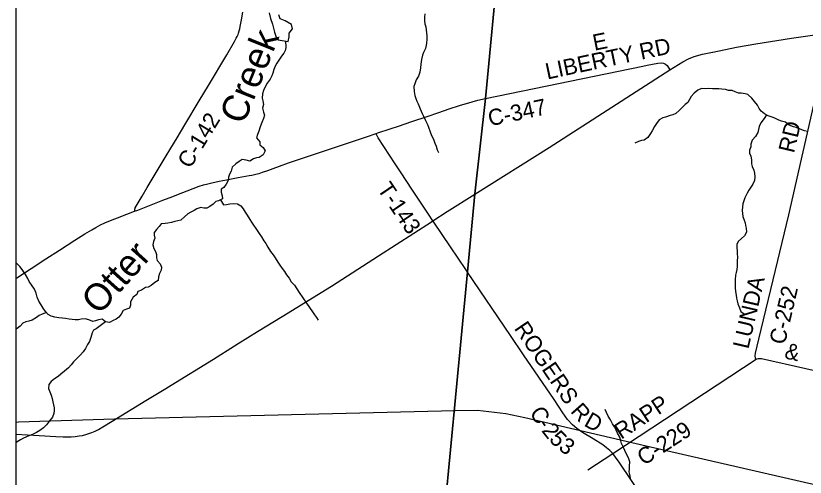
# Model space of a CAD drawing. Extents: x 0 to 34, y 0 to 22.
# Drawn here: x 2.1 to 3.488, y 15.74 to 16.551 of the extents above; entities that cross this region are included whole.
import ezdxf

# ---------------------------------------------------------------- set-up
doc = ezdxf.new("R2010")
doc.units = 0
for name, color, linetype in [('GM_X_Corporation', 7, 'Continuous'), ('GM_X_County_Road', 7, 'Continuous'), ('GM_X_County_Road_Text', 7, 'Continuous'), ('GM_X_Minor_Lake', 7, 'Continuous'), ('GM_X_Minor_River', 7, 'Continuous'), ('GM_X_Minor_River_Text', 7, 'Continuous'), ('GM_X_Rail_Line', 7, 'Continuous'), ('GM_X_State_Location', 7, 'Continuous'), ('GM_X_State_Route', 7, 'Continuous'), ('GM_X_Township_Road', 7, 'Continuous'), ('GM_X_Township_Road_Text', 7, 'Continuous'), ('SH_Data', 7, 'Continuous')]:
    doc.layers.add(name, color=color, linetype=linetype)

msp = doc.modelspace()

# ---------------------------------------------------------------- linework, layer by layer
at = {"layer": 'GM_X_Corporation'}
for points in [[(2.8444, 15.5792), (2.8939, 16.1007), (2.9069, 16.2381), (2.9254, 16.4061), (2.988, 17.0603), (3.0331, 17.5172), (3.0637, 17.8164), (3.0931, 18.1263), (3.1112, 18.3014), (3.1559, 18.7686), (3.1859, 19.0395), (3.2287, 19.5029), (3.2417, 19.6403), (3.2592, 19.8236), (3.2953, 20.1573), (3.3575, 20.7908), (3.3687, 20.9), (2.1, 20.9), (2.1, 14.1)], [(8.9, 20.9), (3.3687, 20.9), (3.3575, 20.7908), (3.2953, 20.1573), (3.2592, 19.8236), (3.2417, 19.6403), (3.2287, 19.5029), (3.1859, 19.0395), (3.1559, 18.7686), (3.1112, 18.3014), (3.0931, 18.1263), (3.0637, 17.8164), (3.0331, 17.5172), (2.988, 17.0603), (2.9254, 16.4061), (2.9069, 16.2381), (2.8939, 16.1007), (2.8444, 15.5792)]]:
    msp.add_lwpolyline(points, dxfattribs=at)
msp.add_lwpolyline([(2.1, 18.2085), (2.1, 15.0365), (2.12, 15.0353), (2.1206, 15.0353), (2.1394, 15.0344), (2.1436, 15.0342), (2.148, 15.0339), (2.791, 14.9974), (2.8444, 15.5792), (2.8939, 16.1007), (2.9069, 16.2381), (2.9254, 16.4061), (2.988, 17.0603), (3.0331, 17.5172), (3.0637, 17.8164), (3.0931, 18.1263), (3.0252, 18.1335), (2.8083, 18.1509), (2.4093, 18.1831), (2.1311, 18.2055)], close=True, dxfattribs=at)
at = {"layer": 'GM_X_County_Road'}
msp.add_line((3.1053, 15.7527), (3.1492, 15.7812), dxfattribs=at)
for points in [[(2.3089, 16.2074), (2.309, 16.2091), (2.3091, 16.2106), (2.3093, 16.2116), (2.3096, 16.2126), (2.31, 16.2138), (2.3131, 16.2193), (2.3221, 16.2342), (2.3312, 16.2495), (2.3468, 16.2756), (2.3628, 16.3022), (2.3725, 16.3185), (2.3835, 16.3369), (2.3969, 16.3593), (2.4224, 16.402), (2.4385, 16.4289), (2.4707, 16.4828), (2.4844, 16.5061), (2.4876, 16.5118), (2.4893, 16.5151), (2.4906, 16.5182), (2.4915, 16.5206), (2.4928, 16.5251), (2.4938, 16.5285), (2.4946, 16.5325), (2.4968, 16.5441), (2.4993, 16.5579)], [(3.4013, 15.9472), (3.4005, 15.9491), (3.3995, 15.953), (3.4, 15.9576), (3.4061, 15.9827), (3.4354, 16.1039), (3.4589, 16.2013), (3.5314, 16.5205)], [(2.9255, 16.4059), (3.2023, 16.4627), (3.2098, 16.4642)], [(3.2098, 16.4642), (3.2285, 16.4679), (3.2351, 16.4686), (3.2388, 16.4679), (3.2419, 16.4664), (3.2449, 16.4638), (3.2499, 16.4562)], [(2.1, 16.0891), (2.102, 16.0904), (2.1271, 16.1066), (2.1531, 16.1236), (2.1768, 16.139), (2.2039, 16.1567), (2.2212, 16.1676), (2.2334, 16.175), (2.2407, 16.1791), (2.249, 16.1834), (2.2568, 16.187), (2.2695, 16.1923), (2.2787, 16.196), (2.2952, 16.2022), (2.3089, 16.2074), (2.3144, 16.2095), (2.341, 16.22), (2.3587, 16.2268), (2.3758, 16.2334), (2.383, 16.2363), (2.412, 16.2476), (2.4221, 16.2514), (2.4301, 16.254), (2.4375, 16.256), (2.4445, 16.2577), (2.4576, 16.2603), (2.4701, 16.2626), (2.4911, 16.2667), (2.5103, 16.2702), (2.5151, 16.2712), (2.5197, 16.2722), (2.5241, 16.2732), (2.5277, 16.2742), (2.5339, 16.2761), (2.5428, 16.2792), (2.5525, 16.2829), (2.5637, 16.2871), (2.5792, 16.2925), (2.6148, 16.3047), (2.6481, 16.3158), (2.6709, 16.3233), (2.7163, 16.3386), (2.7335, 16.3444), (2.7365, 16.3454), (2.758, 16.3527), (2.7725, 16.3574), (2.796, 16.3652), (2.8233, 16.3744), (2.8435, 16.3812), (2.8619, 16.3874), (2.88, 16.3935), (2.9022, 16.3999), (2.9124, 16.4027), (2.9255, 16.4059)], [(3.1492, 15.7812), (3.1442, 15.7865), (3.1383, 15.7916), (3.1316, 15.7966), (3.1148, 15.8072), (3.0961, 15.8185), (3.0864, 15.8252), (3.0788, 15.8318), (3.0698, 15.8415), (3.0618, 15.8528), (3.0461, 15.8761), (2.9926, 15.9551), (2.9695, 15.9892), (2.894, 16.1004)], [(3.1492, 15.7812), (3.4013, 15.9472), (3.4056, 15.9484), (3.4107, 15.9484), (3.4889, 15.9308), (3.6071, 15.9041), (3.932, 15.83), (4.1105, 15.7887), (4.468, 15.7031), (4.4755, 15.701), (4.4802, 15.6984), (4.484, 15.6949)], [(3.2487, 15.6355), (3.1608, 15.7663), (3.1543, 15.7752), (3.1492, 15.7812)]]:
    msp.add_lwpolyline(points, dxfattribs=at)
at = {"layer": 'GM_X_Minor_Lake'}
msp.add_lwpolyline([(2.5454, 16.5563), (2.5476, 16.5466), (2.551, 16.5368), (2.5547, 16.5223), (2.5578, 16.5135), (2.5612, 16.5093), (2.5786, 16.506), (2.5808, 16.5143), (2.5806, 16.5206), (2.5866, 16.5282), (2.5846, 16.5362), (2.5737, 16.5423), (2.565, 16.5461), (2.5621, 16.5533)], dxfattribs=at)
at = {"layer": 'GM_X_Minor_River'}
for points in [[(2.8189, 16.5548), (2.8184, 16.5489), (2.8183, 16.5426), (2.8193, 16.5371), (2.8208, 16.5321), (2.8216, 16.5264), (2.8221, 16.5213), (2.8226, 16.5158), (2.8225, 16.5109), (2.8219, 16.5027), (2.8203, 16.4936), (2.8167, 16.4868), (2.8151, 16.4819), (2.8133, 16.4746), (2.812, 16.4662), (2.8111, 16.46), (2.8102, 16.4524), (2.8076, 16.4454), (2.8039, 16.4387), (2.8013, 16.4319), (2.7999, 16.4268), (2.8003, 16.4184), (2.8017, 16.411), (2.8029, 16.406), (2.8051, 16.4011), (2.8071, 16.3963), (2.8108, 16.3879), (2.8146, 16.3794), (2.8165, 16.3747), (2.8199, 16.3674), (2.8236, 16.3603), (2.8254, 16.3555), (2.8283, 16.3473), (2.8309, 16.3406), (2.834, 16.3341), (2.8364, 16.3274), (2.8389, 16.3221), (2.8409, 16.3158), (2.8433, 16.311)], [(2.5741, 16.5068), (2.5746, 16.4965), (2.574, 16.4916), (2.5712, 16.4854), (2.5669, 16.4805), (2.5634, 16.4749), (2.5591, 16.4682), (2.556, 16.4629), (2.5536, 16.4567), (2.5516, 16.4506), (2.5502, 16.4457), (2.5472, 16.4399), (2.5421, 16.4329), (2.5378, 16.425), (2.5353, 16.42), (2.5334, 16.4139), (2.5331, 16.4063), (2.5345, 16.4016), (2.5352, 16.3953), (2.5339, 16.3889), (2.5357, 16.382), (2.5373, 16.3766), (2.5353, 16.3704), (2.5325, 16.3634), (2.5297, 16.3559), (2.5271, 16.3483), (2.525, 16.3425), (2.5231, 16.3366), (2.5287, 16.3295), (2.5292, 16.3242), (2.5346, 16.3197), (2.5383, 16.3136), (2.5346, 16.3068), (2.5277, 16.3018), (2.5229, 16.3015), (2.5177, 16.2999), (2.5116, 16.2958), (2.5051, 16.2975), (2.4981, 16.2985), (2.4929, 16.2952), (2.487, 16.2909), (2.4802, 16.2848), (2.4788, 16.2782), (2.4758, 16.2725), (2.474, 16.2673), (2.4733, 16.2619), (2.4696, 16.2554), (2.4659, 16.2495), (2.4611, 16.2466), (2.4612, 16.2413), (2.463, 16.2344), (2.4633, 16.2295), (2.4563, 16.2258), (2.4516, 16.2245), (2.4467, 16.2199), (2.4413, 16.216), (2.4358, 16.2132), (2.4303, 16.2131), (2.425, 16.2144), (2.4184, 16.2118), (2.4133, 16.2089), (2.4077, 16.2059), (2.4027, 16.2032), (2.3963, 16.1978), (2.3901, 16.192), (2.3848, 16.1904), (2.3796, 16.1893), (2.3737, 16.1875), (2.3674, 16.1863), (2.3627, 16.186), (2.3554, 16.1856), (2.3519, 16.1807), (2.3476, 16.1753), (2.343, 16.1702), (2.3431, 16.1655), (2.3443, 16.1603), (2.3423, 16.1543), (2.3409, 16.1486), (2.3427, 16.1419), (2.3453, 16.1366), (2.3471, 16.1312), (2.3475, 16.1257), (2.3488, 16.121), (2.354, 16.115), (2.3564, 16.1091), (2.3557, 16.1039), (2.3527, 16.0979), (2.3509, 16.0921), (2.3504, 16.0858), (2.3443, 16.0819), (2.3381, 16.0767), (2.3326, 16.074), (2.3278, 16.0735), (2.3207, 16.0688), (2.3147, 16.0663), (2.3125, 16.0608), (2.3062, 16.0562), (2.3019, 16.0483), (2.3018, 16.0422), (2.2998, 16.0369), (2.2946, 16.0355)], [(3.4914, 16.348), (3.4865, 16.3488), (3.479, 16.3518), (3.472, 16.3547), (3.4669, 16.3561), (3.4597, 16.3588), (3.4529, 16.3641), (3.4459, 16.3662), (3.441, 16.3676), (3.4345, 16.3714), (3.4296, 16.3733), (3.4228, 16.3756), (3.4162, 16.3787), (3.4102, 16.3836), (3.4068, 16.3884), (3.4036, 16.3939), (3.3983, 16.4004), (3.3936, 16.4067), (3.3868, 16.4126), (3.3819, 16.4143), (3.3749, 16.4153), (3.3702, 16.4155), (3.3643, 16.4178), (3.3594, 16.4197), (3.3528, 16.4201), (3.3477, 16.4215), (3.3409, 16.4225), (3.3359, 16.4231), (3.3295, 16.4229), (3.3246, 16.4229), (3.3179, 16.4237), (3.3126, 16.4228), (3.3056, 16.4236), (3.2986, 16.4206), (3.2925, 16.4155), (3.2872, 16.4091), (3.2845, 16.4042), (3.2814, 16.3991), (3.2767, 16.3953), (3.2708, 16.3897), (3.2662, 16.3848), (3.2601, 16.3793), (3.2551, 16.3774), (3.2502, 16.3759), (3.2422, 16.3731), (3.2373, 16.3717)], [(3.4198, 16.377), (3.4152, 16.3707), (3.4097, 16.3632), (3.4064, 16.3566), (3.4054, 16.3511), (3.4041, 16.346), (3.4004, 16.3392), (3.3943, 16.3327), (3.3922, 16.3257), (3.392, 16.321), (3.3897, 16.3148), (3.3897, 16.3095), (3.3919, 16.3045), (3.3932, 16.2977), (3.3935, 16.2912), (3.3945, 16.2861), (3.3975, 16.2799), (3.3984, 16.2745), (3.3989, 16.2683), (3.3987, 16.2617), (3.3958, 16.255), (3.3918, 16.2499), (3.3884, 16.2447), (3.3857, 16.2396), (3.3817, 16.2314), (3.3795, 16.2261), (3.3778, 16.2204), (3.3772, 16.2151), (3.377, 16.2087), (3.3775, 16.2036), (3.3781, 16.1985), (3.3803, 16.192), (3.3818, 16.1873), (3.3825, 16.1825), (3.3836, 16.1776), (3.3843, 16.1708), (3.3809, 16.1641), (3.3758, 16.1596), (3.3699, 16.1542), (3.3674, 16.1489), (3.3675, 16.1437), (3.3681, 16.1371), (3.3678, 16.1324), (3.3684, 16.1265), (3.3678, 16.1202), (3.3679, 16.1153), (3.3683, 16.1102), (3.3673, 16.1051), (3.366, 16.1), (3.3648, 16.0949), (3.3644, 16.0869), (3.3645, 16.0791), (3.3645, 16.0731), (3.3652, 16.0662), (3.3661, 16.0598), (3.367, 16.0545), (3.3678, 16.0497), (3.3694, 16.0444), (3.3719, 16.0374), (3.3745, 16.0309), (3.3803, 16.0271)], [(3.2373, 16.3717), (3.231, 16.3683), (3.2261, 16.362), (3.2226, 16.3564), (3.2188, 16.3492), (3.2155, 16.3441), (3.2112, 16.3373), (3.2045, 16.3326), (3.1996, 16.3317), (3.1946, 16.3304), (3.1884, 16.327)], [(2.46, 16.2277), (2.4653, 16.2188), (2.4701, 16.2195), (2.4764, 16.2207), (2.4833, 16.221), (2.4897, 16.2205), (2.4957, 16.217), (2.4998, 16.2118), (2.5033, 16.2058), (2.5069, 16.2004), (2.5113, 16.1931), (2.5143, 16.1883), (2.5178, 16.1832), (2.5219, 16.1772), (2.5276, 16.1682), (2.5317, 16.1628), (2.5363, 16.1557), (2.5395, 16.1507), (2.5433, 16.1442), (2.548, 16.1369), (2.5522, 16.1311), (2.5559, 16.1254), (2.5607, 16.1181), (2.5639, 16.1129), (2.5685, 16.1069), (2.5722, 16.1015), (2.576, 16.0958), (2.5806, 16.09), (2.5843, 16.0833), (2.5901, 16.0775), (2.5943, 16.0712), (2.5984, 16.0646), (2.6047, 16.0552), (2.6112, 16.0458), (2.6214, 16.0304), (2.6249, 16.0253), (2.6288, 16.0204), (2.6314, 16.0157)], [(2.2946, 16.0355), (2.2887, 16.0331), (2.2853, 16.0266), (2.2812, 16.0211), (2.2764, 16.0178), (2.2712, 16.0152), (2.2645, 16.0117), (2.2575, 16.0132), (2.2517, 16.0175), (2.2454, 16.0168), (2.2404, 16.0146), (2.2357, 16.0137), (2.2285, 16.0165), (2.2219, 16.018), (2.2148, 16.0175), (2.21, 16.0163), (2.2043, 16.0167), (2.199, 16.017), (2.1939, 16.0177), (2.1875, 16.0191), (2.1821, 16.0196), (2.1755, 16.0203), (2.1685, 16.0212), (2.1622, 16.0228), (2.157, 16.0257), (2.1525, 16.0313), (2.1484, 16.0369), (2.1445, 16.0428), (2.1408, 16.0495), (2.1375, 16.0562), (2.1357, 16.0633), (2.133, 16.0702), (2.1276, 16.0781), (2.1236, 16.0838), (2.1212, 16.0892), (2.1173, 16.0965), (2.1125, 16.1034), (2.1075, 16.1097), (2.1009, 16.1165), (2.1, 16.1174)], [(2.1541, 16.0293), (2.1463, 16.0267), (2.1413, 16.0243), (2.1363, 16.0204), (2.1288, 16.0158), (2.1231, 16.0144), (2.1177, 16.0129), (2.1126, 16.0109), (2.1075, 16.0053), (2.1025, 16.0014), (2.1, 16.0002)], [(2.2575, 16.0132), (2.2413, 16.0005), (2.2365, 15.9985), (2.234, 15.9935), (2.2317, 15.9857), (2.2295, 15.9783), (2.2262, 15.9729), (2.2227, 15.9661), (2.2182, 15.9605), (2.2137, 15.9547), (2.2069, 15.9482), (2.2017, 15.9426), (2.1976, 15.9375), (2.1928, 15.9321), (2.1856, 15.9261), (2.1793, 15.9207), (2.1743, 15.9168), (2.1679, 15.9128), (2.1623, 15.9079), (2.158, 15.9025), (2.1577, 15.8955), (2.1599, 15.8896), (2.1621, 15.8838), (2.1637, 15.8783), (2.1653, 15.8724), (2.1665, 15.867), (2.1676, 15.8619), (2.1677, 15.8568), (2.167, 15.8515), (2.1644, 15.8451), (2.1594, 15.8387), (2.1539, 15.8316), (2.1487, 15.8265), (2.1424, 15.8219), (2.1364, 15.8186), (2.1293, 15.8151), (2.1228, 15.8122), (2.1136, 15.8082), (2.1084, 15.8052), (2.1023, 15.8021), (2.1, 15.8004)], [(3.1808, 15.7381), (3.1793, 15.7444), (3.1782, 15.7492), (3.179, 15.7545), (3.179, 15.7594), (3.1794, 15.7668), (3.1772, 15.7736), (3.1736, 15.7803), (3.1704, 15.7869), (3.168, 15.792), (3.1648, 15.7987), (3.1635, 15.8038), (3.162, 15.8103), (3.1577, 15.8173), (3.1556, 15.8222), (3.1524, 15.8285), (3.1491, 15.8337), (3.1455, 15.8405), (3.1412, 15.8473), (3.1382, 15.8538), (3.1361, 15.8587)]]:
    msp.add_lwpolyline(points, dxfattribs=at)
at = {"layer": 'GM_X_Rail_Line'}
for points in [[(2.1, 15.8368), (2.1046, 15.8372), (2.2734, 15.8423), (2.8725, 15.857)], [(2.8725, 15.857), (2.9115, 15.8579), (2.9613, 15.8516), (2.9946, 15.8445), (3.2081, 15.795), (3.7492, 15.6705), (3.9302, 15.6314), (4.3, 15.5466), (4.6063, 15.4754), (4.9134, 15.4063), (4.9924, 15.381), (5.0264, 15.3654), (5.0626, 15.3427), (5.087, 15.3222), (5.1229, 15.2868)]]:
    msp.add_lwpolyline(points, dxfattribs=at)
at = {"layer": 'GM_X_State_Route'}
msp.add_line((2.491, 15.9748), (2.5251, 15.9958), dxfattribs=at)
for points in [[(3.3246, 16.4875), (3.3251, 16.4876), (3.3669, 16.4959), (3.4009, 16.502), (3.4637, 16.5117), (3.5004, 16.5174), (3.5118, 16.5191), (3.5205, 16.5201), (3.524, 16.5203), (3.5314, 16.5205), (3.5434, 16.5201), (3.5546, 16.5188), (3.5629, 16.5173), (3.5726, 16.515), (3.582, 16.5121), (3.5917, 16.5084), (3.9393, 16.3414), (4.2118, 16.2104), (4.221, 16.2064), (4.2322, 16.2024), (4.2412, 16.1999), (4.2523, 16.1971), (4.2797, 16.1912), (4.3303, 16.1801)], [(3.2499, 16.4562), (3.2726, 16.4706), (3.2824, 16.4757), (3.2922, 16.4796), (3.3073, 16.4838), (3.3246, 16.4875)], [(2.9071, 16.2378), (3.0373, 16.3195), (3.2499, 16.4562)], [(2.5251, 15.9958), (2.5681, 16.0222), (2.655, 16.0759), (2.7377, 16.1292), (2.8305, 16.189), (2.8331, 16.1907), (2.8583, 16.2073), (2.9071, 16.2378)], [(2.1, 15.8156), (2.1412, 15.8131), (2.1704, 15.8114), (2.1831, 15.8106), (2.1911, 15.8105), (2.1976, 15.8108), (2.2044, 15.8113), (2.2112, 15.8122), (2.2173, 15.8133), (2.223, 15.8146), (2.2283, 15.8163), (2.2338, 15.8183), (2.2395, 15.8208), (2.2453, 15.8237), (2.2531, 15.8281), (2.2696, 15.8381), (2.3285, 15.8745), (2.364, 15.8958), (2.3731, 15.9014), (2.4475, 15.9476), (2.4842, 15.9706), (2.491, 15.9748)]]:
    msp.add_lwpolyline(points, dxfattribs=at)
at = {"layer": 'GM_X_Township_Road'}
for points in [[(2.8331, 16.1907), (2.8252, 16.2025), (2.7975, 16.2445), (2.7765, 16.2767), (2.7671, 16.2907), (2.7371, 16.3368), (2.7352, 16.3401), (2.7342, 16.3426), (2.7335, 16.3444)], [(2.894, 16.1004), (2.8911, 16.1048), (2.8639, 16.1449), (2.8493, 16.1666), (2.8347, 16.1882), (2.8331, 16.1907)]]:
    msp.add_lwpolyline(points, dxfattribs=at)
at = {"layer": 'SH_Data'}
msp.add_line((2.1, 20.9), (2.1, 14.1), dxfattribs=at)

# ---------------------------------------------------------------- texts
at = {"layer": 'GM_X_County_Road_Text'}
for s, height, rotation, p in [('E', 0.0284, 11.3125, (3.1171, 16.4898)), ('LIBERTY RD', 0.02841, 11.9063, (3.0342, 16.4392)), ('C-347', 0.02841, 11.9025, (2.9334, 16.3569)), ('C-142', 0.02841, 58.6102, (2.4066, 16.2811)), ('RD', 0.02841, 76.5615, (3.4678, 16.3086)), ('LUNDA', 0.02841, 76.9617, (3.3877, 15.964)), ('C-252', 0.02841, 76.9016, (3.4517, 15.9715)), ('ROGERS', 0.02841, 304.0729, (2.975, 16.0015)), ('&', 0.0284, 347.4712, (3.4498, 15.949)), ('RAPP', 0.02841, 33.3837, (3.1641, 15.8054)), ('C', 0.0284, 302.7439, (3.0022, 15.8531)), ('R', 0.0284, 311.3545, (3.0737, 15.8549)), ('D', 0.0284, 330.7532, (3.0971, 15.831)), ('-', 0.0284, 303.7985, (3.0152, 15.833)), ('2', 0.0284, 308.4054, (3.0231, 15.8213)), ('C-229', 0.02841, 33.2314, (3.204, 15.7593)), ('5', 0.0284, 314.0856, (3.036, 15.8053)), ('3', 0.0284, 324.0271, (3.0523, 15.7892))]:
    msp.add_text(s, height=height, rotation=rotation, dxfattribs=at).set_placement(p)
at = {"layer": 'GM_X_Minor_River_Text'}
for s, rotation, p in [('Creek', 68.0214, (2.5006, 16.3581)), ('Otter', 48.0304, (2.2462, 16.0233))]:
    msp.add_text(s, height=0.04735, rotation=rotation, dxfattribs=at).set_placement(p)
at = {"layer": 'GM_X_State_Location'}
for s in ['s', 'r']:
    msp.add_text(s, height=0.0000947, dxfattribs=at).set_placement((2.1275, 15.7955))
at = {"layer": 'GM_X_Township_Road_Text'}
msp.add_text('T-143', height=0.02841, rotation=304.1594, dxfattribs=at).set_placement((2.7345, 16.2466))

doc.saveas('drawing.dxf')
